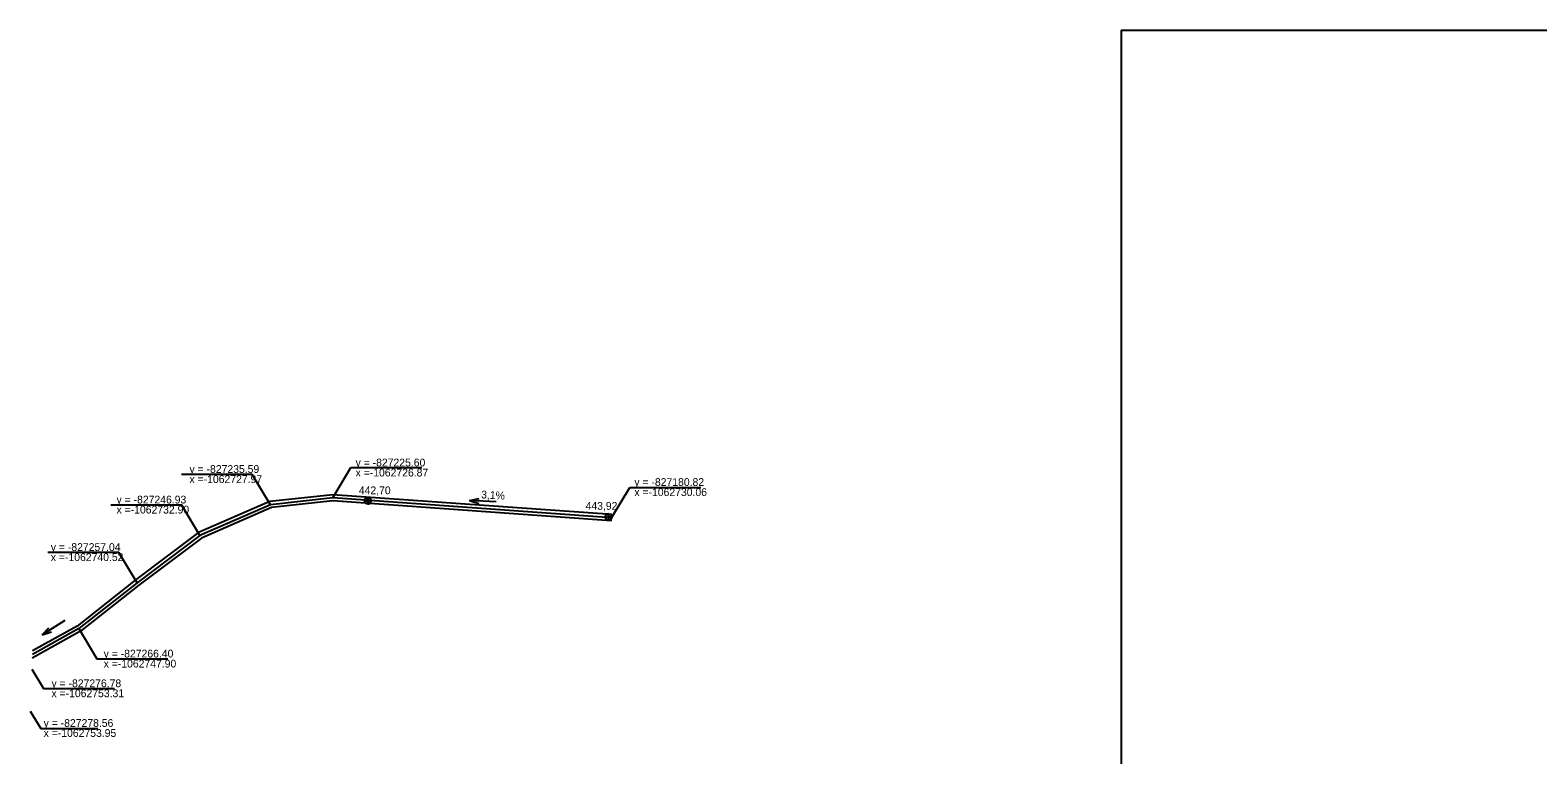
# Model space of a CAD drawing. Extents: x -438410 to -437811, y -1133174 to -1132817.
# Drawn here: x -438406.1 to -438163.9, y -1133015.5 to -1132899 of the extents above; entities that cross this region are included whole.
import ezdxf

# ---------------------------------------------------------------- set-up
doc = ezdxf.new("R2010")
doc.units = 0
for name, color, linetype in [('9 - příkop B', 7, 'Continuous'), ('Default', 7, 'Continuous'), ('Vrstva 1', 7, 'Continuous')]:
    doc.layers.add(name, color=color, linetype=linetype)

# ---------------------------------------------------------------- blocks, each defined once
blk = doc.blocks.new('A$C7F8213DF')
at = {"layer": 'Default'}
for p, q in [((-5.1, 0), (5.1, 0)), ((0, 5.1), (0, -5.1)), ((5.1, 0), (0, 0)), ((0, 0), (0, -5.1))]:
    blk.add_line(p, q, dxfattribs=at)
blk.add_lwpolyline([(-5.1, 0), (0, 0), (0, 5.1)], dxfattribs=at)
blk.add_circle((0, 0), 5.1, dxfattribs=at)
for start, end in [(90, 180), (270, 0)]:
    blk.add_arc((0, 0), 5.1, start, end, dxfattribs=at)

msp = doc.modelspace()

# ---------------------------------------------------------------- linework, layer by layer
at = {"layer": '9 - příkop B'}
for p, q in [((-438367.45, -1132975.27), (-438378.79, -1132980.2)), ((-438357.46, -1132974.17), (-438367.45, -1132975.27)), ((-438312.68, -1132977.36), (-438357.46, -1132974.17)), ((-438335.5, -1132974.6), (-438333.94, -1132974.3)), ((-438331.2, -1132974.84), (-438335.5, -1132974.6)), ((-438335.5, -1132974.6), (-438333.99, -1132975.07)), ((-438312.72, -1132977.86), (-438312.61, -1132976.86)), ((-438378.79, -1132980.2), (-438388.9, -1132987.81)), ((-438388.9, -1132987.81), (-438398.26, -1132995.19)), ((-438400.51, -1132993.87), (-438404.14, -1132996.21)), ((-438398.26, -1132995.19), (-438405.71, -1132999.34)), ((-438404.14, -1132996.21), (-438403.06, -1132995.05)), ((-438404.14, -1132996.21), (-438402.63, -1132995.7))]:
    msp.add_line(p, q, dxfattribs=at)
for points in [[(-438312.72, -1132977.86), (-438357.45, -1132974.67), (-438367.32, -1132975.75), (-438378.54, -1132980.63), (-438388.6, -1132988.21), (-438397.98, -1132995.61), (-438405.74, -1132999.92)], [(-438312.64, -1132976.86), (-438357.47, -1132973.67), (-438367.58, -1132974.78), (-438379.05, -1132979.76), (-438389.21, -1132987.42), (-438398.54, -1132994.77), (-438405.69, -1132998.75)]]:
    msp.add_lwpolyline(points, dxfattribs=at)
at = {"layer": 'Vrstva 1'}
for p, q in [((-438230.82, -1132899.01), (-437810.82, -1132899.01)), ((-438230.82, -1132899.01), (-438230.82, -1133049.01)), ((-438370.38, -1132970.4), (-438381.78, -1132970.4)), ((-438367.45, -1132975.27), (-438370.38, -1132970.4)), ((-438357.46, -1132974.17), (-438354.53, -1132969.31)), ((-438354.53, -1132969.31), (-438343.14, -1132969.31)), ((-438312.68, -1132977.36), (-438309.75, -1132972.5)), ((-438309.75, -1132972.5), (-438298.36, -1132972.5)), ((-438381.72, -1132975.34), (-438393.11, -1132975.34)), ((-438378.79, -1132980.2), (-438381.72, -1132975.34)), ((-438391.83, -1132982.95), (-438403.23, -1132982.95)), ((-438388.9, -1132987.81), (-438391.83, -1132982.95)), ((-438398.26, -1132995.19), (-438395.33, -1133000.05)), ((-438405.81, -1133001.72), (-438403.93, -1133004.83)), ((-438395.33, -1133000.05), (-438383.94, -1133000.05)), ((-438403.93, -1133004.83), (-438392.54, -1133004.83)), ((-438406.07, -1133008.43), (-438404.37, -1133011.22)), ((-438404.37, -1133011.22), (-438395.22, -1133011.22))]:
    msp.add_line(p, q, dxfattribs=at)

# ---------------------------------------------------------------- block references
at = {"layer": '9 - příkop B', "xscale": 0.1, "yscale": 0.10000000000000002}
for p in [(-438351.83, -1132974.64), (-438313.16, -1132977.26)]:
    msp.add_blockref('A$C7F8213DF', p, dxfattribs=at)

# ---------------------------------------------------------------- texts
at = {"layer": '9 - příkop B'}
for s, rotation, p in [('442,70', 359.9998, (-438353.27, -1132973.59)), ('3,1%', 356.7762, (-438333.65, -1132974.25)), ('443,92', 359.9998, (-438316.85, -1132976.09))]:
    msp.add_text(s, height=1.25, rotation=rotation, dxfattribs=at).set_placement(p)
at = {"layer": 'Vrstva 1'}
for s, p in [('y = -827225.60', (-438353.79, -1132969.12)), ('y = -827235.59', (-438380.47, -1132970.17)), ('x =-1062726.87', (-438353.79, -1132970.74)), ('x =-1062727.97', (-438380.47, -1132971.79)), ('y = -827180.82', (-438309.01, -1132972.26)), ('x =-1062730.06', (-438309.01, -1132973.88)), ('y = -827246.93', (-438392.19, -1132975.08)), ('x =-1062732.90', (-438392.19, -1132976.69)), ('y = -827257.04', (-438402.75, -1132982.71)), ('x =-1062740.52', (-438402.75, -1132984.33)), ('y = -827266.40', (-438394.26, -1132999.83)), ('x =-1062747.90', (-438394.26, -1133001.44)), ('y = -827276.78', (-438402.64, -1133004.6)), ('x =-1062753.31', (-438402.64, -1133006.21)), ('y = -827278.56', (-438403.9, -1133010.98)), ('x =-1062753.95', (-438403.9, -1133012.59))]:
    msp.add_text(s, height=1.25, dxfattribs=at).set_placement(p)

doc.saveas('drawing.dxf')
